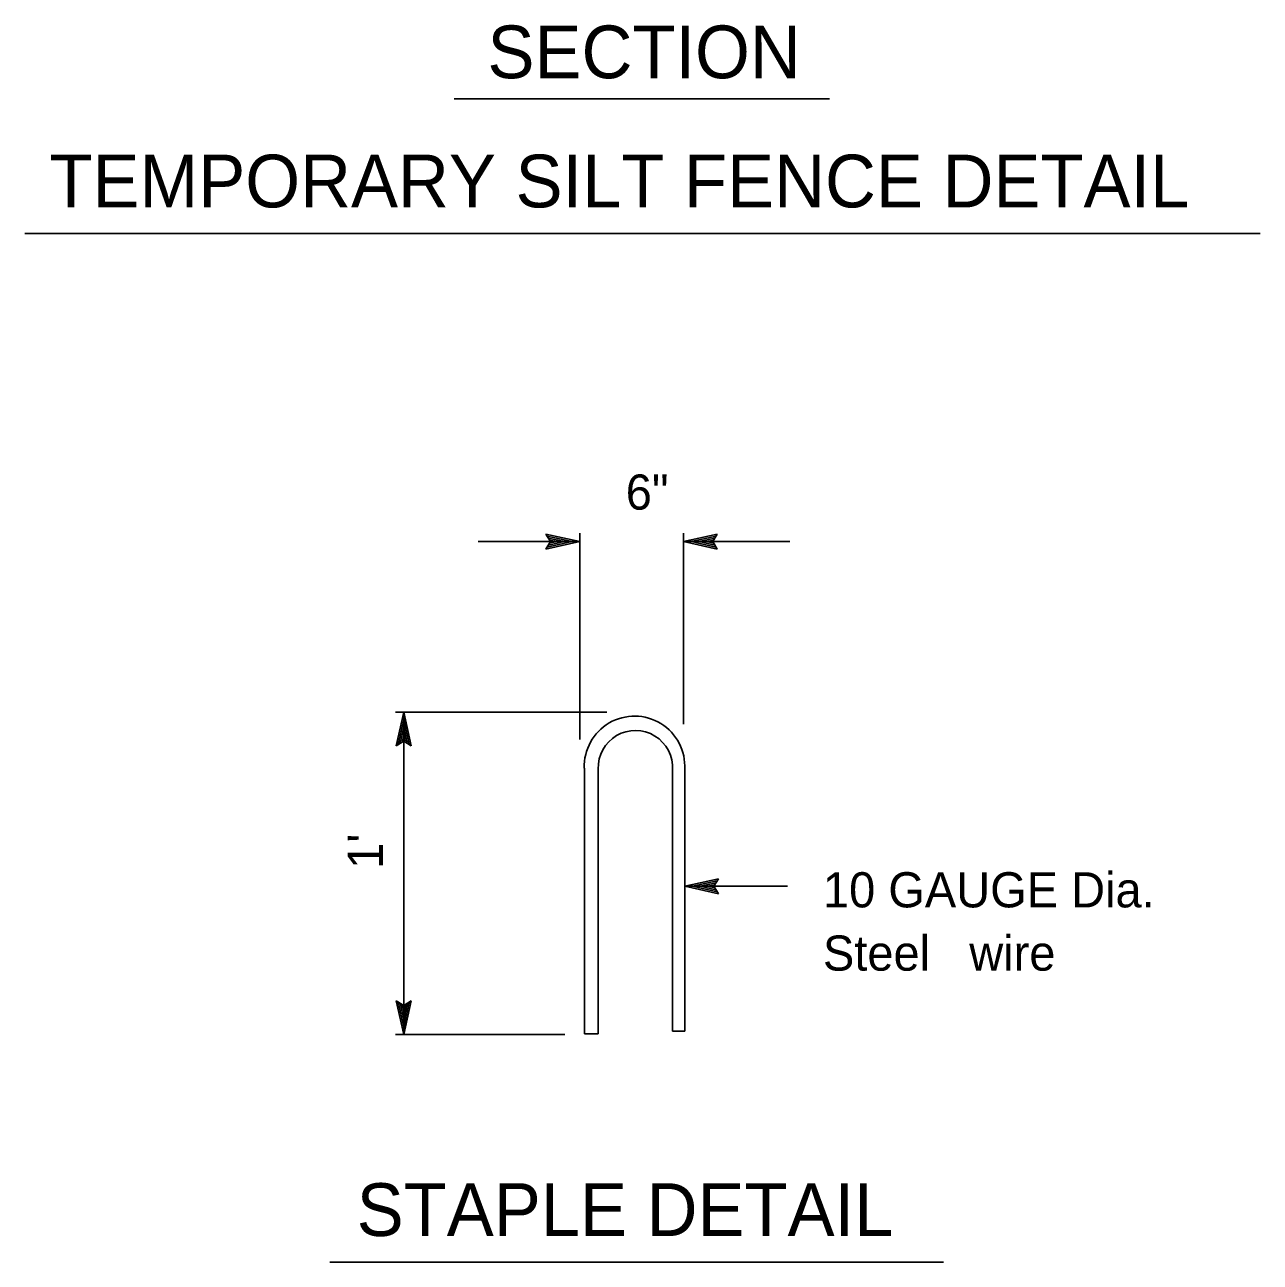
# Model space of a CAD drawing. Extents: x 6708945 to 6710368, y 1871409 to 1872338.
# Drawn here: x 6710148.5 to 6710359.4, y 1871525.7 to 1871736.9 of the extents above; entities that cross this region are included whole.
import ezdxf

# ---------------------------------------------------------------- set-up
doc = ezdxf.new("R2010")
doc.units = 0
for name, color, linetype in [('56 Stg 3 Anno', 7, 'Continuous'), ('57 Undefined', 7, 'Continuous'), ('60 Nongeo Data', 7, 'Continuous')]:
    doc.layers.add(name, color=color, linetype=linetype)

msp = doc.modelspace()

# ---------------------------------------------------------------- linework, layer by layer
at = {"layer": '56 Stg 3 Anno'}
for p, q in [((6710243.21, 1871648.67), (6710237.45, 1871649.94)), ((6710237.45, 1871649.94), (6710237.45, 1871649.94)), ((6710237.45, 1871649.94), (6710238.22, 1871648.67)), ((6710243.22, 1871614.9), (6710243.22, 1871650.11)), ((6710260.93, 1871617.52), (6710260.93, 1871650.11)), ((6710266.69, 1871649.95), (6710260.93, 1871648.67)), ((6710265.92, 1871648.67), (6710266.69, 1871649.95)), ((6710266.69, 1871649.95), (6710266.69, 1871649.95)), ((6710243.13, 1871648.67), (6710225.89, 1871648.67)), ((6710238.22, 1871648.67), (6710237.45, 1871647.38)), ((6710237.45, 1871647.38), (6710243.21, 1871648.67)), ((6710237.66, 1871647.72), (6710241.88, 1871648.67)), ((6710241.87, 1871648.67), (6710237.67, 1871649.6)), ((6710240.56, 1871648.67), (6710237.84, 1871649.27)), ((6710237.88, 1871648.07), (6710240.56, 1871648.67)), ((6710238.05, 1871648.4), (6710239.23, 1871648.66)), ((6710239.23, 1871648.66), (6710238.07, 1871648.92)), ((6710243.21, 1871648.67), (6710243.21, 1871648.67)), ((6710260.93, 1871648.67), (6710260.93, 1871648.67)), ((6710260.93, 1871648.67), (6710266.69, 1871647.39)), ((6710261.36, 1871648.67), (6710279.07, 1871648.67)), ((6710266.48, 1871649.61), (6710262.26, 1871648.67)), ((6710262.27, 1871648.66), (6710266.47, 1871647.74)), ((6710266.26, 1871649.27), (6710263.58, 1871648.67)), ((6710263.58, 1871648.67), (6710266.29, 1871648.07)), ((6710266.09, 1871648.93), (6710264.91, 1871648.67)), ((6710264.91, 1871648.67), (6710266.07, 1871648.41)), ((6710266.69, 1871647.39), (6710265.92, 1871648.67)), ((6710237.45, 1871647.38), (6710237.45, 1871647.38)), ((6710266.69, 1871647.39), (6710266.69, 1871647.39)), ((6710247.86, 1871619.57), (6710211.74, 1871619.57)), ((6710211.89, 1871613.81), (6710213.18, 1871619.57)), ((6710212.23, 1871614.02), (6710213.18, 1871618.25)), ((6710213.18, 1871564.52), (6710213.18, 1871619.57)), ((6710213.18, 1871619.57), (6710213.18, 1871619.57)), ((6710213.18, 1871619.57), (6710214.45, 1871613.81)), ((6710213.18, 1871618.24), (6710214.11, 1871614.04)), ((6710212.58, 1871614.25), (6710213.17, 1871616.92)), ((6710213.17, 1871616.92), (6710213.78, 1871614.21)), ((6710213.18, 1871614.58), (6710211.89, 1871613.81)), ((6710211.89, 1871613.81), (6710211.89, 1871613.81)), ((6710212.91, 1871614.42), (6710213.17, 1871615.6)), ((6710213.17, 1871615.6), (6710213.43, 1871614.44)), ((6710214.45, 1871613.81), (6710213.18, 1871614.58)), ((6710214.45, 1871613.81), (6710214.45, 1871613.81)), ((6710261.13, 1871589.84), (6710266.89, 1871591.12)), ((6710262.46, 1871589.85), (6710266.66, 1871590.77)), ((6710266.89, 1871591.12), (6710266.12, 1871589.84)), ((6710266.89, 1871591.12), (6710266.89, 1871591.12)), ((6710278.68, 1871589.84), (6710261.13, 1871589.84)), ((6710266.89, 1871588.56), (6710261.13, 1871589.84)), ((6710261.13, 1871589.84), (6710261.13, 1871589.84)), ((6710266.68, 1871588.9), (6710262.45, 1871589.84)), ((6710263.78, 1871589.84), (6710266.49, 1871590.44)), ((6710266.46, 1871589.24), (6710263.78, 1871589.84)), ((6710265.11, 1871589.84), (6710266.27, 1871590.1)), ((6710266.29, 1871589.58), (6710265.11, 1871589.84)), ((6710266.12, 1871589.84), (6710266.89, 1871588.56)), ((6710266.89, 1871588.56), (6710266.89, 1871588.56)), ((6710213.18, 1871564.52), (6710211.9, 1871570.28)), ((6710211.9, 1871570.28), (6710211.9, 1871570.28)), ((6710211.9, 1871570.28), (6710213.18, 1871569.51)), ((6710213.17, 1871565.85), (6710212.24, 1871570.05)), ((6710213.18, 1871567.17), (6710212.58, 1871569.88)), ((6710213.18, 1871568.49), (6710212.92, 1871569.66)), ((6710213.18, 1871569.51), (6710214.46, 1871570.28)), ((6710214.46, 1871570.28), (6710213.18, 1871564.52)), ((6710214.12, 1871570.07), (6710213.18, 1871565.84)), ((6710213.78, 1871569.84), (6710213.18, 1871567.17)), ((6710213.44, 1871569.67), (6710213.18, 1871568.49)), ((6710214.46, 1871570.28), (6710214.46, 1871570.28)), ((6710240.68, 1871564.52), (6710211.74, 1871564.52)), ((6710213.18, 1871564.52), (6710213.18, 1871564.52))]:
    msp.add_line(p, q, dxfattribs=at)
at = {"layer": '57 Undefined'}
for p, q in [((6710221.78, 1871724.22), (6710285.84, 1871724.22)), ((6710148.46, 1871701.22), (6710359.39, 1871701.22)), ((6710200.53, 1871525.68), (6710305.33, 1871525.68))]:
    msp.add_line(p, q, dxfattribs=at)
at = {"layer": '60 Nongeo Data'}
for p, q in [((6710244, 1871564.66), (6710244, 1871609.99)), ((6710246.36, 1871564.66), (6710246.36, 1871609.85)), ((6710259.04, 1871565.11), (6710259.04, 1871609.69)), ((6710261.13, 1871565.11), (6710261.13, 1871609.78)), ((6710244, 1871564.66), (6710246.36, 1871564.66)), ((6710259.04, 1871565.11), (6710261.13, 1871565.11))]:
    msp.add_line(p, q, dxfattribs=at)
for centre, major_axis in [((6710252.57, 1871610.3), (0, -8.58)), ((6710252.71, 1871610.08), (0, -6.35))]:
    msp.add_ellipse(centre, major_axis=major_axis, ratio=0.999991, start_param=1.510257, end_param=4.748244, dxfattribs=at)

# ---------------------------------------------------------------- texts
at = {"layer": '57 Undefined'}
for s, height, p in [('SECTION', 9, (6710227.46, 1871727.74)), ('TEMPORARY SILT FENCE DETAIL', 9, (6710152.68, 1871705.7)), ('6"', 6, (6710251.07, 1871654.12)), ('10 GAUGE Dia.', 6, (6710284.74, 1871586.24)), ('Steel   wire', 6, (6710284.74, 1871575.44)), ('STAPLE DETAIL', 9, (6710205.13, 1871530.16))]:
    msp.add_text(s, height=height, dxfattribs=at).set_placement(p)
msp.add_text("1'", height=6, rotation=90, dxfattribs=at).set_placement((6710209.61, 1871592.83))

doc.saveas('drawing.dxf')
